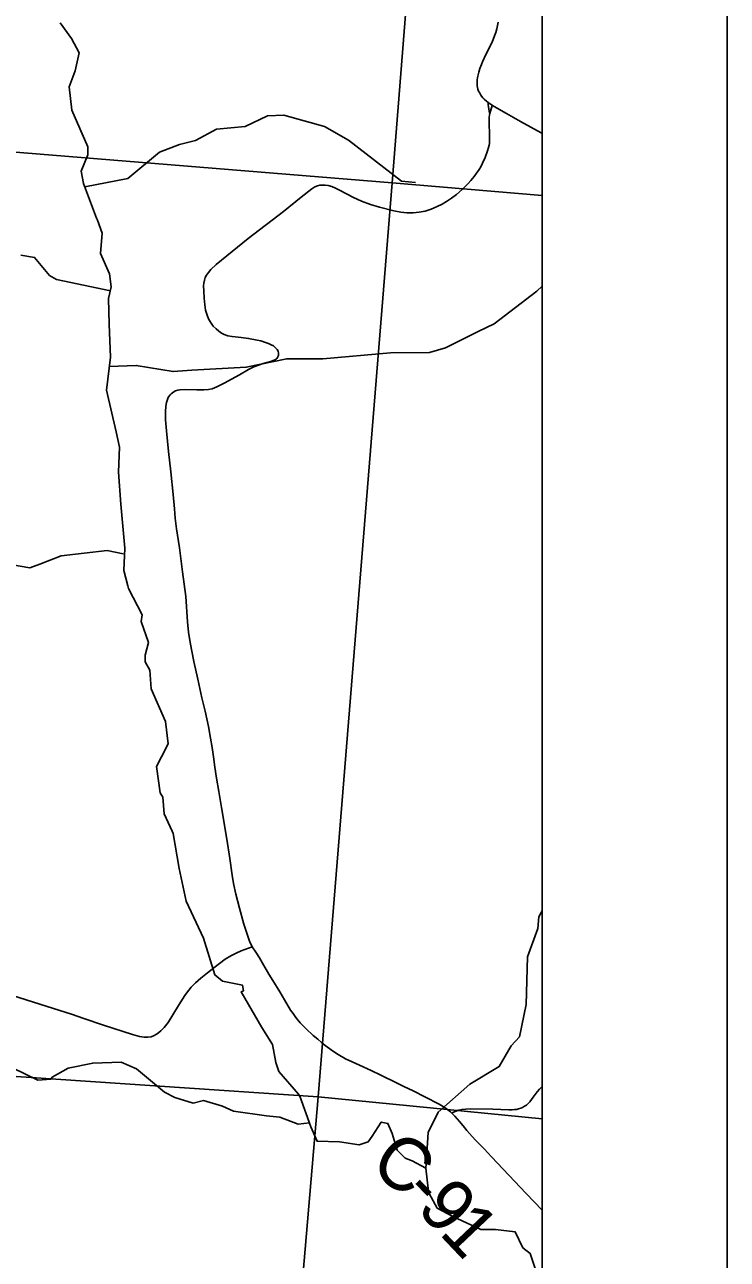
# Model space of a CAD drawing. Extents: x 0 to 42, y 0 to 22.
# Drawn here: x 8.62 to 9, y 15.878 to 16.545 of the extents above; entities that cross this region are included whole.
import ezdxf

# ---------------------------------------------------------------- set-up
doc = ezdxf.new("R2010")
doc.units = 0
for name, color, linetype in [('GM_X_County_Road', 7, 'Continuous'), ('GM_X_County_Road_Text', 7, 'Continuous'), ('GM_X_Minor_River', 7, 'Continuous'), ('GM_X_Section', 7, 'Continuous'), ('GM_X_Township_Road', 7, 'Continuous'), ('GM_X_Unincorporated', 7, 'Continuous'), ('SH_Cut_Line', 7, 'Continuous'), ('SH_Data', 7, 'Continuous')]:
    doc.layers.add(name, color=color, linetype=linetype)

msp = doc.modelspace()

# ---------------------------------------------------------------- linework, layer by layer
at = {"layer": 'GM_X_County_Road'}
for points in [[(8.87615, 16.54645), (8.8759, 16.54464), (8.8755, 16.54285), (8.87495, 16.54088), (8.8743, 16.53903), (8.87292, 16.53561), (8.86968, 16.52932), (8.86775, 16.52512), (8.86715, 16.52359), (8.86641, 16.5215), (8.8658, 16.51948)], [(8.8658, 16.51948), (8.86539, 16.51803), (8.86512, 16.51666), (8.86492, 16.51524), (8.86487, 16.51429), (8.86486, 16.51303), (8.86493, 16.51213), (8.86511, 16.51114), (8.8653, 16.51037), (8.86569, 16.50932), (8.86614, 16.50844), (8.86674, 16.50736), (8.86728, 16.50656), (8.86802, 16.50566), (8.86866, 16.50492), (8.86996, 16.50378), (8.87082, 16.50314), (8.87147, 16.50265), (8.87299, 16.50167), (8.87406, 16.50098), (8.88071, 16.49725), (8.88838, 16.49288), (8.89938, 16.48674), (8.9, 16.48641)], [(8.74339, 16.04716), (8.7419, 16.05024), (8.73892, 16.05933), (8.73644, 16.06806), (8.73456, 16.07567), (8.73332, 16.08132), (8.73249, 16.08577), (8.73128, 16.09487), (8.72976, 16.10532), (8.7268, 16.12245), (8.72543, 16.13106), (8.72405, 16.13815), (8.72326, 16.14416), (8.72253, 16.14977), (8.72175, 16.15485), (8.7209, 16.15985), (8.71969, 16.16621), (8.71789, 16.17436), (8.71623, 16.18162), (8.71398, 16.19162), (8.71188, 16.20121), (8.70991, 16.21149), (8.70899, 16.21714), (8.70849, 16.22274), (8.70752, 16.23633), (8.70579, 16.24959), (8.70408, 16.26267), (8.70256, 16.2729), (8.70183, 16.2786), (8.70139, 16.28365), (8.70068, 16.29141), (8.69935, 16.30364), (8.69825, 16.31468), (8.69706, 16.32583), (8.69649, 16.33168), (8.69655, 16.33606), (8.69678, 16.33909), (8.69705, 16.34105), (8.69739, 16.34226), (8.69777, 16.34326), (8.6982, 16.3441), (8.699, 16.34517), (8.69958, 16.34582), (8.70034, 16.34641), (8.70113, 16.34692), (8.70196, 16.34734), (8.70316, 16.34772), (8.70427, 16.34789), (8.7075, 16.34806), (8.71342, 16.34789), (8.7172, 16.34787), (8.71983, 16.34813), (8.72172, 16.34857), (8.72425, 16.34957), (8.7283, 16.35161), (8.73643, 16.3561), (8.74132, 16.35889), (8.74425, 16.36029), (8.74684, 16.36132), (8.74934, 16.36212), (8.75267, 16.36303), (8.75436, 16.36352), (8.75561, 16.36408), (8.75632, 16.36452), (8.75673, 16.36494), (8.757, 16.36536), (8.75739, 16.36616), (8.75753, 16.36674), (8.75757, 16.36736), (8.75751, 16.36793), (8.75735, 16.36856), (8.75714, 16.36912), (8.75681, 16.36966), (8.75603, 16.37062), (8.75485, 16.37162), (8.75367, 16.37227), (8.75211, 16.373), (8.75063, 16.37355), (8.74803, 16.37433), (8.746, 16.37485), (8.74142, 16.37568), (8.73739, 16.37619), (8.73254, 16.37674), (8.73023, 16.37716), (8.72823, 16.37785), (8.72672, 16.3786), (8.72527, 16.37963), (8.72388, 16.38088), (8.72238, 16.38242), (8.72093, 16.38442), (8.71983, 16.38631), (8.71901, 16.38821), (8.71822, 16.39096), (8.71777, 16.39382), (8.71742, 16.39747), (8.71718, 16.40146), (8.71715, 16.40411), (8.71725, 16.40562), (8.71756, 16.40725), (8.71803, 16.40864), (8.7187, 16.4099), (8.71969, 16.41127), (8.72111, 16.41292), (8.72393, 16.41557), (8.74125, 16.42966), (8.76035, 16.44425), (8.76985, 16.45199), (8.77563, 16.45653), (8.77728, 16.45752), (8.7787, 16.45808), (8.77989, 16.45839), (8.78144, 16.45854), (8.7827, 16.45852), (8.78446, 16.45828), (8.78647, 16.45774), (8.78833, 16.45694), (8.79055, 16.45581), (8.79802, 16.45186), (8.80236, 16.44979), (8.80731, 16.44806), (8.81211, 16.44667), (8.81986, 16.44465), (8.82373, 16.44385), (8.82698, 16.4436), (8.83034, 16.44357), (8.83351, 16.44383), (8.83684, 16.44447), (8.84013, 16.44553), (8.84335, 16.44687), (8.84599, 16.44824), (8.84839, 16.44966), (8.85097, 16.45142), (8.85368, 16.45346), (8.85678, 16.45614), (8.8584, 16.45767), (8.86001, 16.45934), (8.86153, 16.46108), (8.86328, 16.46323), (8.8645, 16.46497), (8.86589, 16.46692), (8.86679, 16.46843), (8.86785, 16.47034), (8.86926, 16.47343), (8.87043, 16.47694), (8.87098, 16.47881), (8.87132, 16.48007), (8.8715, 16.48095), (8.8716, 16.48206), (8.87159, 16.48482), (8.87138, 16.49305), (8.87144, 16.49497), (8.8716, 16.49646), (8.87172, 16.49721), (8.87237, 16.49961), (8.87273, 16.50081), (8.87299, 16.50167)], [(8.87172, 16.49721), (8.87142, 16.4985), (8.87116, 16.49962), (8.87097, 16.50061), (8.87086, 16.502), (8.87082, 16.50314)], [(8.6139, 16.02087), (8.63603, 16.01389), (8.64573, 16.01072), (8.65249, 16.00844), (8.66304, 16.00478), (8.67873, 15.99988), (8.68258, 15.9988), (8.68496, 15.9984), (8.68704, 15.99834), (8.68876, 15.99861), (8.69008, 15.99915), (8.69198, 16.00023), (8.69404, 16.00187), (8.69586, 16.00368), (8.69793, 16.00623), (8.70364, 16.01544), (8.70567, 16.01884), (8.70707, 16.02087), (8.7079, 16.02215), (8.7104, 16.02532), (8.7128, 16.02778), (8.71564, 16.03022), (8.71741, 16.03162), (8.71928, 16.03312), (8.72265, 16.03586), (8.72884, 16.04048), (8.73187, 16.04231), (8.73478, 16.04382), (8.73745, 16.04504), (8.74339, 16.04716)], [(8.74339, 16.04716), (8.74531, 16.04425), (8.74733, 16.04121), (8.749, 16.03838), (8.75241, 16.03238), (8.75451, 16.02892), (8.75823, 16.02279), (8.76078, 16.01853), (8.76414, 16.01299), (8.76544, 16.01113), (8.76694, 16.00896), (8.76928, 16.00612), (8.7725, 16.00281), (8.77639, 15.99928), (8.77876, 15.99727), (8.78077, 15.99554), (8.78279, 15.99396), (8.78527, 15.992), (8.78676, 15.99099), (8.78982, 15.98898), (8.79383, 15.98669), (8.79745, 15.98499), (8.80139, 15.98318), (8.8076, 15.98031), (8.81281, 15.97785), (8.82138, 15.9738), (8.82536, 15.9718), (8.83027, 15.96934), (8.83657, 15.96613), (8.8444, 15.96214), (8.84763, 15.96019), (8.8504, 15.95812), (8.85113, 15.95742), (8.85291, 15.95572), (8.85534, 15.95285), (8.85725, 15.95049), (8.85924, 15.94803), (8.8621, 15.94481), (8.86403, 15.94279), (8.86858, 15.93801), (8.87259, 15.9338), (8.89139, 15.91395), (8.9, 15.90492)]]:
    msp.add_lwpolyline(points, dxfattribs=at)
at = {"layer": 'GM_X_Minor_River'}
for points in [[(8.63973, 16.54614), (8.6458, 16.5376), (8.64997, 16.53001), (8.64771, 16.52013), (8.6445, 16.51158), (8.64602, 16.49905), (8.65456, 16.47912), (8.65456, 16.47494), (8.65097, 16.46601), (8.6523, 16.45937), (8.65932, 16.44058), (8.65989, 16.43963), (8.66236, 16.4326), (8.66142, 16.42159), (8.66635, 16.41058), (8.66712, 16.40356), (8.6658, 16.39729), (8.66619, 16.38342), (8.66677, 16.36557), (8.6647, 16.34771), (8.66983, 16.32531), (8.67173, 16.31696), (8.67118, 16.30347), (8.67233, 16.28619), (8.67462, 16.26245), (8.67406, 16.2503), (8.67615, 16.24213), (8.67653, 16.24062), (8.68393, 16.22638), (8.68336, 16.22277), (8.68735, 16.21157), (8.68565, 16.20473), (8.68565, 16.20113), (8.68812, 16.19657), (8.68888, 16.18651), (8.69647, 16.16886), (8.698, 16.1567), (8.69441, 16.14967), (8.69176, 16.14454), (8.69367, 16.13029), (8.69518, 16.12802), (8.69576, 16.1189), (8.70012, 16.1096), (8.70069, 16.10827), (8.70392, 16.08948), (8.70772, 16.07182), (8.71702, 16.05189), (8.72328, 16.03196), (8.72726, 16.02855), (8.73805, 16.02648), (8.73862, 16.02344), (8.73749, 16.02287), (8.74849, 16.00351), (8.75436, 15.9944), (8.75607, 15.98472), (8.75778, 15.97978), (8.76839, 15.96764), (8.76915, 15.96651), (8.77503, 15.94999), (8.77845, 15.94221), (8.79057, 15.94185), (8.80117, 15.94016), (8.80609, 15.94188), (8.80817, 15.94492), (8.81309, 15.95253), (8.81668, 15.95177), (8.81896, 15.94627)], [(8.65297, 16.45759), (8.67627, 16.46201), (8.69328, 16.47626), (8.70406, 16.48045), (8.71276, 16.48255), (8.7241, 16.48864), (8.73962, 16.49019), (8.75172, 16.4959), (8.76042, 16.49629), (8.78237, 16.49008), (8.79544, 16.48271), (8.82403, 16.46058), (8.8316, 16.45983)], [(8.66688, 16.4015), (8.63774, 16.40752), (8.63395, 16.40978), (8.6258, 16.41944), (8.61842, 16.42075)], [(8.6662, 16.36061), (8.68073, 16.36114), (8.7006, 16.35777), (8.71082, 16.35855), (8.74014, 16.36012), (8.76208, 16.36471), (8.78157, 16.36475), (8.81808, 16.36785), (8.83908, 16.36808), (8.84778, 16.37056), (8.86536, 16.37951), (8.87406, 16.38351), (8.89712, 16.40118), (8.9, 16.40402)], [(8.67366, 16.25931), (8.66495, 16.26119), (8.64017, 16.2583), (8.62864, 16.25373), (8.62334, 16.25182), (8.60442, 16.25501), (8.58151, 16.26918), (8.57015, 16.27921), (8.56258, 16.28128), (8.55235, 16.29435), (8.54269, 16.30267), (8.53133, 16.31061), (8.52393, 16.32804), (8.51787, 16.33448), (8.51635, 16.34149), (8.51559, 16.34377), (8.51388, 16.34869), (8.49761, 16.35511)], [(8.83717, 15.92754), (8.83841, 15.94694), (8.84389, 15.95795), (8.86089, 15.97296), (8.87678, 15.98247), (8.8832, 15.99367), (8.88773, 15.99861), (8.89131, 16.01607), (8.89203, 16.04167), (8.89769, 16.05704), (8.89825, 16.0633), (8.9, 16.0666)], [(8.77425, 15.9522), (8.76822, 15.95131), (8.75837, 15.95509), (8.75118, 15.95584), (8.73319, 15.95847), (8.72732, 15.96112), (8.71709, 15.96414), (8.71141, 15.9628), (8.70157, 15.96582), (8.69607, 15.96866), (8.68092, 15.98136), (8.67259, 15.98495), (8.65725, 15.98436), (8.644, 15.98168), (8.6353, 15.97672), (8.63454, 15.97577), (8.62754, 15.97519), (8.6139, 15.98181)], [(8.81896, 15.94627), (8.82162, 15.93735), (8.82597, 15.93298), (8.82976, 15.93166), (8.83715, 15.92768), (8.83867, 15.91496), (8.83905, 15.91401), (8.84323, 15.90604), (8.85175, 15.9015), (8.8669, 15.8945), (8.87485, 15.89451), (8.88545, 15.8932), (8.88962, 15.88466), (8.8936, 15.88163), (8.89873, 15.86606), (8.9, 15.8604)]]:
    msp.add_lwpolyline(points, dxfattribs=at)
at = {"layer": 'GM_X_Section'}
for points in [[(8.30008, 17.00734), (8.8004, 16.96848), (8.85894, 16.96397), (8.81895, 16.45969), (8.25964, 16.50525)], [(8.25964, 16.50525), (8.81895, 16.45969), (8.77896, 15.9662), (8.21749, 16.00402)], [(8.21749, 16.00402), (8.77896, 15.9662), (8.73537, 15.45585), (8.17393, 15.50423), (8.21703, 15.99853)]]:
    msp.add_lwpolyline(points, close=True, dxfattribs=at)
at = {"layer": 'GM_X_Township_Road'}
msp.add_lwpolyline([(8.05023, 14.1), (8.9, 14.1), (8.9, 16.95771), (8.669, 16.9761), (8.30518, 17.00518), (8.2967, 17.00562), (8.26133, 16.54947), (8.24231, 16.32059), (8.17227, 15.49063), (8.16983, 15.46634), (8.16945, 15.45935), (8.16837, 15.44612), (8.1628, 15.37905), (8.15761, 15.31908), (8.1512, 15.24132), (8.08338, 14.51358), (8.06868, 14.30702)], close=True, dxfattribs=at)
msp.add_lwpolyline([(8.85113, 15.95742), (8.85207, 15.95785), (8.85347, 15.9585), (8.8544, 15.95882), (8.855, 15.95899), (8.85668, 15.95925), (8.85885, 15.95948), (8.86144, 15.95961), (8.87332, 15.95956), (8.88202, 15.9592), (8.88375, 15.9592), (8.88507, 15.95927), (8.88614, 15.95938), (8.88722, 15.95961), (8.88841, 15.95997), (8.88937, 15.96042), (8.89046, 15.96105), (8.89152, 15.96174), (8.89328, 15.96339), (8.89522, 15.966), (8.89729, 15.96891), (8.89851, 15.9703), (8.89941, 15.97121), (8.9, 15.97169)], dxfattribs=at)
at = {"layer": 'GM_X_Unincorporated'}
for points in [[(8.9, 16.45296), (8.9, 16.96072), (8.85894, 16.96397), (8.81895, 16.45969)], [(8.9, 15.9543), (8.9, 16.45296), (8.81895, 16.45969), (8.77896, 15.9662)], [(8.9, 15.43991), (8.9, 15.9543), (8.77896, 15.9662), (8.73537, 15.45585)]]:
    msp.add_lwpolyline(points, close=True, dxfattribs=at)
at = {"layer": 'SH_Cut_Line'}
msp.add_lwpolyline([(8.9, 14.1), (8.9, 20.00639), (8.75955, 20.01746), (8.65628, 20.02413), (8.5294, 20.03351), (8.48531, 19.43126), (8.46517, 19.12289), (8.46366, 19.1008), (8.46152, 19.07253), (8.46207, 19.06399), (8.4621, 19.05934), (8.4614, 19.04662), (8.46117, 19.04011), (8.46085, 19.02695), (8.42127, 18.51405), (8.38769, 18.10646), (8.32232, 17.47301), (8.30468, 17.09885), (8.29856, 17.02621), (8.2967, 17.00562), (8.26133, 16.54947), (8.24231, 16.32059), (8.17227, 15.49063)], dxfattribs=at)
at = {"layer": 'SH_Data'}
for p, q in [((9, 21), (9, 14)), ((8.9, 20.9), (8.9, 14.1))]:
    msp.add_line(p, q, dxfattribs=at)

# ---------------------------------------------------------------- texts
at = {"layer": 'GM_X_County_Road_Text'}
for s, rotation, p in [('C', 323.43688, (8.80584, 15.92696)), ('-', 313.61723, (8.82362, 15.91392)), ('9', 312.73454, (8.83159, 15.90555)), ('1', 313.49925, (8.84375, 15.8924))]:
    msp.add_text(s, height=0.02841, rotation=rotation, dxfattribs=at).set_placement(p)

doc.saveas('drawing.dxf')
